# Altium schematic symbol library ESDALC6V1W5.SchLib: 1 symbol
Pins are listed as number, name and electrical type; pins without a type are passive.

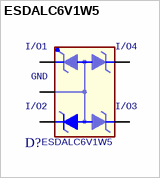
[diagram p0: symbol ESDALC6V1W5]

## ESDALC6V1W5
designator D?
footprint ST_SOT323-5L
pins: 1 I/O1, 2 GND, 3 I/O2, 4 I/O3, 5 I/O4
